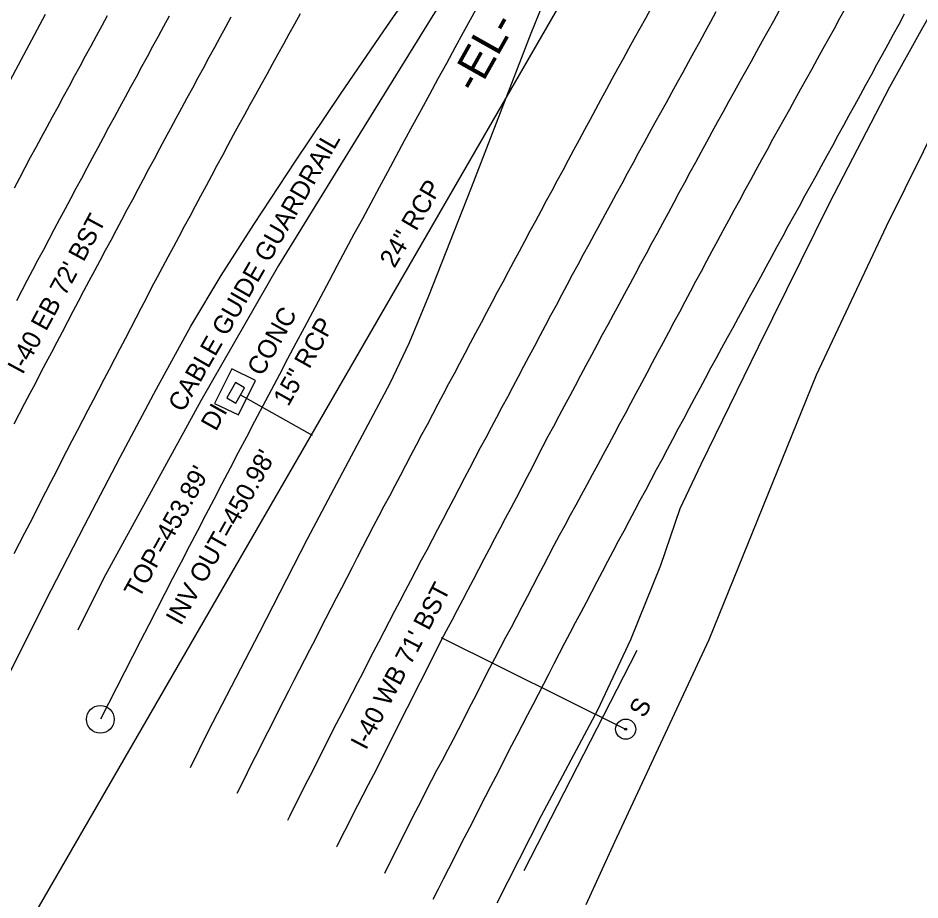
# Model space of a CAD drawing. Extents: x 2074109 to 2077820, y 741079 to 746031.
# Drawn here: x 2074752.4 to 2074948, y 741950.3 to 742141.5 of the extents above; entities that cross this region are included whole.
import ezdxf

# ---------------------------------------------------------------- set-up
doc = ezdxf.new("R2010")
doc.units = 0
for name, color, linetype in [('Exist Guardrail', 7, 'Continuous'), ('Exist Guardrail Cable Guide Rail', 7, 'Continuous'), ('Exist Guardrail Cable Guide Rail Text', 7, 'Continuous'), ('Exist Horizontal Alignment', 7, 'Continuous'), ('Exist Horizontal Alignment Direction Label', 7, 'Continuous'), ('Exist Horizontal Alignment Point', 7, 'Continuous'), ('Exist Other Culture Sign', 7, 'Continuous'), ('Exist Other Culture Sign Text', 7, 'Continuous'), ('Exist Roads EOP', 7, 'Continuous'), ('Exist Roads EOP Text', 7, 'Continuous'), ('Exist Roads EOT', 7, 'Continuous'), ('Exist Structure Minor Drop Inlet', 7, 'Continuous'), ('Exist Structure Minor Drop Inlet Text', 7, 'Continuous'), ('Exist Structure Minor Drop Inlet Top Elevation', 7, 'Continuous'), ('Exist Structure Minor Paved Ditch or Gutter', 7, 'Continuous'), ('Exist Structure Minor Paved Ditch or Gutter Text', 7, 'Continuous'), ('Exist Structure Minor Pipes RCP 15 Inch', 7, 'Continuous'), ('Exist Structure Minor Pipes RCP 15 Inch Invert', 7, 'Continuous'), ('Exist Structure Minor Pipes RCP 15 Inch Text', 7, 'Continuous'), ('Exist Structure Minor Pipes RCP 24 Inch', 7, 'Continuous'), ('Exist Structure Minor Pipes RCP 24 Inch Text', 7, 'Continuous'), ('Exist Vegetation Woods Line', 7, 'Continuous')]:
    doc.layers.add(name, color=color, linetype=linetype)

msp = doc.modelspace()

# ---------------------------------------------------------------- linework, layer by layer
at = {"layer": 'Exist Guardrail'}
msp.add_lwpolyline([(2074886.58, 742004.39), (2074862.07, 741956.61)], dxfattribs=at)
at = {"layer": 'Exist Guardrail Cable Guide Rail'}
msp.add_lwpolyline([(2074899.36, 742232.91), (2074888.78, 742216.41), (2074876.27, 742195.78), (2074859.16, 742168.78), (2074842.38, 742142.08), (2074825.57, 742114.96), (2074808.9, 742087.84), (2074792.03, 742058.51), (2074770.99, 742020.02), (2074765.4, 742008.78)], dxfattribs=at)
at = {"layer": 'Exist Horizontal Alignment'}
msp.add_arc((2079979.02, 739333.44), 5846.83, 150.58124, 152.982068, dxfattribs=at)
at = {"layer": 'Exist Horizontal Alignment Point'}
msp.add_circle((2074770.28, 741989.47), 3, dxfattribs=at)
at = {"layer": 'Exist Other Culture Sign'}
msp.add_line((2074884.22, 741987.29), (2074844.2, 742007.16), dxfattribs=at)
for radius in [2.18, 0.24]:
    msp.add_circle((2074884.17, 741987.33), radius, dxfattribs=at)
at = {"layer": 'Exist Roads EOP'}
for points in [[(2075045.28, 742485.48), (2075032.39, 742461.82), (2075017.41, 742432.2), (2075008.62, 742415.56), (2074994.4, 742390.44), (2074976.29, 742358.27), (2074960.6, 742330.46), (2074947.27, 742306.52), (2074935.38, 742284.89), (2074921.31, 742258.95), (2074908.74, 742236.47), (2074898.47, 742217.63), (2074887.04, 742193.79), (2074875.51, 742167.59), (2074863.59, 742138.18), (2074850.64, 742104.73), (2074841.42, 742081.23), (2074837.2, 742071.06), (2074833.01, 742062.28), (2074824.64, 742046.55), (2074815.15, 742028.51), (2074804.68, 742008.24), (2074793.6, 741986.73), (2074789.72, 741978.96)], [(2075094.13, 742370.13), (2075069.1, 742335.88), (2075044.09, 742299.32), (2075030.48, 742279.57), (2075015.99, 742257.41), (2075007.67, 742243.82), (2075000.77, 742231.34), (2074992.02, 742216.02), (2074980.6, 742196.16), (2074968.94, 742175.62), (2074957.17, 742154.61), (2074948.54, 742139.39), (2074941.35, 742126.55), (2074928.28, 742101.28), (2074912.89, 742070.17), (2074900.43, 742044.7), (2074895.91, 742035.09), (2074891.74, 742022.83), (2074885.19, 742006.69), (2074878.07, 741991.46), (2074865.85, 741968.56), (2074856.22, 741949.59)], [(2074750.85, 741999.99), (2074758.48, 742015.22), (2074766.83, 742031.47), (2074774.6, 742046.3), (2074782.43, 742061.13), (2074789.86, 742074.68), (2074796.45, 742085.69), (2074803.58, 742096.75), (2074812.61, 742110.46), (2074822.37, 742125.04), (2074831.71, 742138.74), (2074841.22, 742152.47)]]:
    msp.add_lwpolyline(points, dxfattribs=at)
at = {"layer": 'Exist Roads EOT'}
for points in [[(2074799.94, 741973.43), (2074801.06, 741975.66), (2074802.18, 741977.9), (2074803.29, 741980.14), (2074804.41, 741982.37), (2074805.53, 741984.61), (2074806.65, 741986.85), (2074807.78, 741989.07), (2074808.92, 741991.3), (2074810.06, 741993.52), (2074811.2, 741995.75), (2074812.33, 741997.97), (2074813.47, 742000.2), (2074814.61, 742002.42), (2074815.75, 742004.65), (2074816.89, 742006.87), (2074818.03, 742009.1), (2074819.17, 742011.33), (2074820.31, 742013.55), (2074821.46, 742015.77), (2074822.61, 742017.99), (2074823.76, 742020.21), (2074824.91, 742022.43), (2074826.06, 742024.65), (2074827.21, 742026.87), (2074828.36, 742029.09), (2074829.51, 742031.31), (2074830.67, 742033.52), (2074831.83, 742035.73), (2074833, 742037.94), (2074834.17, 742040.15), (2074835.33, 742042.36), (2074836.5, 742044.57), (2074837.67, 742046.79), (2074838.83, 742049), (2074840, 742051.21), (2074841.17, 742053.42), (2074842.33, 742055.63), (2074843.51, 742057.84), (2074844.68, 742060.05), (2074845.85, 742062.25), (2074847.02, 742064.46), (2074848.19, 742066.67), (2074849.37, 742068.88), (2074850.54, 742071.09), (2074851.71, 742073.29), (2074852.88, 742075.5), (2074854.05, 742077.71), (2074855.22, 742079.92), (2074856.4, 742082.13), (2074857.57, 742084.33), (2074858.74, 742086.54), (2074859.93, 742088.74), (2074861.11, 742090.94), (2074862.29, 742093.15), (2074863.48, 742095.35), (2074864.66, 742097.55), (2074865.84, 742099.75), (2074867.03, 742101.95), (2074868.21, 742104.15), (2074869.39, 742106.36), (2074870.58, 742108.56), (2074871.77, 742110.76), (2074872.95, 742112.96), (2074874.14, 742115.16), (2074875.32, 742117.36), (2074876.51, 742119.56), (2074877.7, 742121.76), (2074878.88, 742123.96), (2074880.07, 742126.16), (2074881.26, 742128.36), (2074882.47, 742130.55), (2074883.67, 742132.74), (2074884.88, 742134.93), (2074886.09, 742137.12), (2074887.29, 742139.3), (2074888.5, 742141.49), (2074889.71, 742143.68)], [(2074917.39, 742143.03), (2074916.18, 742140.85), (2074914.96, 742138.66), (2074913.75, 742136.47), (2074912.54, 742134.29), (2074911.33, 742132.1), (2074910.12, 742129.91), (2074908.91, 742127.73), (2074907.69, 742125.54), (2074906.48, 742123.35), (2074905.27, 742121.17), (2074904.06, 742118.98), (2074902.86, 742116.79), (2074901.66, 742114.59), (2074900.46, 742112.4), (2074899.27, 742110.2), (2074898.09, 742108), (2074896.9, 742105.8), (2074895.71, 742103.6), (2074894.53, 742101.4), (2074893.34, 742099.2), (2074892.16, 742097), (2074890.97, 742094.8), (2074889.78, 742092.6), (2074888.6, 742090.4), (2074887.41, 742088.2), (2074886.23, 742086), (2074885.04, 742083.8), (2074883.85, 742081.6), (2074882.66, 742079.4), (2074881.47, 742077.2), (2074880.28, 742075), (2074879.1, 742072.8), (2074877.92, 742070.59), (2074876.74, 742068.39), (2074875.56, 742066.18), (2074874.38, 742063.98), (2074873.2, 742061.78), (2074872.02, 742059.57), (2074870.84, 742057.37), (2074869.66, 742055.17), (2074868.48, 742052.96), (2074867.3, 742050.76), (2074866.16, 742048.54), (2074865.01, 742046.31), (2074863.86, 742044.09), (2074862.72, 742041.87), (2074861.56, 742039.66), (2074860.39, 742037.44), (2074859.23, 742035.23), (2074858.07, 742033.02), (2074856.91, 742030.8), (2074855.75, 742028.59), (2074854.59, 742026.38), (2074853.43, 742024.16), (2074852.26, 742021.95), (2074851.1, 742019.74), (2074849.94, 742017.52), (2074848.78, 742015.31), (2074847.61, 742013.1), (2074846.45, 742010.89), (2074845.28, 742008.68), (2074844.11, 742006.47), (2074842.98, 742004.23), (2074841.86, 742002), (2074840.74, 741999.77), (2074839.61, 741997.53), (2074838.49, 741995.3), (2074837.37, 741993.07), (2074836.24, 741990.84), (2074835.12, 741988.6), (2074833.99, 741986.37), (2074832.87, 741984.14), (2074831.75, 741981.9), (2074830.62, 741979.67), (2074829.47, 741977.45), (2074828.32, 741975.23), (2074827.17, 741973.01), (2074826.02, 741970.79), (2074824.9, 741968.56), (2074823.77, 741966.33), (2074822.65, 741964.1), (2074821.52, 741961.86), (2074821.48, 741961.78)], [(2074831.95, 741956.11), (2074833.07, 741958.35), (2074834.19, 741960.58), (2074835.31, 741962.82), (2074836.43, 741965.05), (2074837.55, 741967.28), (2074838.67, 741969.52), (2074839.8, 741971.75), (2074840.92, 741973.99), (2074842.08, 741976.2), (2074843.25, 741978.41), (2074844.42, 741980.62), (2074845.59, 741982.83), (2074846.76, 741985.04), (2074847.92, 741987.25), (2074849.06, 741989.48), (2074850.19, 741991.71), (2074851.32, 741993.93), (2074852.46, 741996.16), (2074853.59, 741998.39), (2074854.72, 742000.62), (2074855.88, 742002.83), (2074857.05, 742005.05), (2074858.21, 742007.26), (2074859.38, 742009.47), (2074860.54, 742011.68), (2074861.71, 742013.89), (2074862.86, 742016.11), (2074864.02, 742018.32), (2074865.18, 742020.54), (2074866.33, 742022.76), (2074867.49, 742024.97), (2074868.65, 742027.19), (2074869.85, 742029.38), (2074871.04, 742031.58), (2074872.23, 742033.78), (2074873.42, 742035.98), (2074874.62, 742038.17), (2074875.81, 742040.37), (2074877, 742042.57), (2074878.19, 742044.76), (2074879.38, 742046.97), (2074880.55, 742049.17), (2074881.73, 742051.38), (2074882.91, 742053.58), (2074884.09, 742055.78), (2074885.27, 742057.99), (2074886.45, 742060.19), (2074887.63, 742062.4), (2074888.81, 742064.6), (2074889.99, 742066.81), (2074891.16, 742069.01), (2074892.34, 742071.22), (2074893.52, 742073.42), (2074894.69, 742075.63), (2074895.87, 742077.83), (2074897.05, 742080.04), (2074898.22, 742082.25), (2074899.4, 742084.45), (2074900.57, 742086.66), (2074901.75, 742088.86), (2074902.93, 742091.07), (2074904.12, 742093.27), (2074905.31, 742095.46), (2074906.51, 742097.66), (2074907.7, 742099.85), (2074908.9, 742102.05), (2074910.09, 742104.25), (2074911.29, 742106.44), (2074912.48, 742108.64), (2074913.68, 742110.83), (2074914.87, 742113.03), (2074916.09, 742115.22), (2074917.3, 742117.4), (2074918.51, 742119.59), (2074919.72, 742121.78), (2074920.93, 742123.96), (2074922.14, 742126.15), (2074923.35, 742128.34), (2074924.56, 742130.53), (2074925.77, 742132.71), (2074926.98, 742134.9), (2074928.19, 742137.09), (2074929.41, 742139.27), (2074930.62, 742141.46), (2074931.83, 742143.64)], [(2074758.35, 742142.29), (2074749.53, 742125.74)], [(2074813.59, 742142.41), (2074812.38, 742140.22), (2074811.17, 742138.03), (2074809.96, 742135.85), (2074808.76, 742133.66), (2074807.55, 742131.47), (2074806.34, 742129.28), (2074805.13, 742127.09), (2074803.93, 742124.9), (2074802.72, 742122.71), (2074801.51, 742120.52), (2074800.3, 742118.33), (2074799.1, 742116.15), (2074797.92, 742113.94), (2074796.74, 742111.74), (2074795.56, 742109.53), (2074794.38, 742107.33), (2074793.19, 742105.13), (2074792.01, 742102.92), (2074790.83, 742100.72), (2074789.65, 742098.52), (2074788.47, 742096.31), (2074787.29, 742094.11), (2074786.11, 742091.91), (2074784.93, 742089.7), (2074783.75, 742087.5), (2074782.57, 742085.3), (2074781.4, 742083.08), (2074780.25, 742080.87), (2074779.1, 742078.65), (2074777.95, 742076.43), (2074776.79, 742074.21), (2074775.64, 742071.99), (2074774.49, 742069.78), (2074773.33, 742067.56), (2074772.18, 742065.34), (2074771.03, 742063.12), (2074769.87, 742060.9), (2074768.72, 742058.69), (2074767.57, 742056.47), (2074766.41, 742054.25), (2074765.26, 742052.03), (2074764.11, 742049.81), (2074762.96, 742047.6), (2074761.81, 742045.37), (2074760.67, 742043.15), (2074759.54, 742040.92), (2074758.4, 742038.7), (2074757.26, 742036.47), (2074756.12, 742034.25), (2074754.98, 742032.02), (2074753.84, 742029.8), (2074752.7, 742027.57), (2074751.56, 742025.35)], [(2074751.62, 742053.56), (2074752.78, 742055.77), (2074753.94, 742057.99), (2074755.1, 742060.2), (2074756.26, 742062.42), (2074757.41, 742064.63), (2074758.57, 742066.85), (2074759.73, 742069.06), (2074760.89, 742071.28), (2074762.05, 742073.5), (2074763.2, 742075.71), (2074764.36, 742077.93), (2074765.53, 742080.14), (2074766.7, 742082.34), (2074767.88, 742084.55), (2074769.06, 742086.75), (2074770.23, 742088.96), (2074771.41, 742091.17), (2074772.59, 742093.37), (2074773.76, 742095.58), (2074774.94, 742097.78), (2074776.12, 742099.99), (2074777.29, 742102.19), (2074778.47, 742104.4), (2074779.65, 742106.6), (2074780.82, 742108.81), (2074781.99, 742111.02), (2074783.16, 742113.23), (2074784.34, 742115.43), (2074785.53, 742117.63), (2074786.73, 742119.83), (2074787.92, 742122.02), (2074789.12, 742124.22), (2074790.31, 742126.41), (2074791.5, 742128.61), (2074792.7, 742130.81), (2074793.89, 742133), (2074795.09, 742135.2), (2074796.28, 742137.39), (2074797.48, 742139.59), (2074798.67, 742141.79)], [(2074751.64, 742104.7), (2074752.82, 742106.9), (2074753.99, 742109.11), (2074755.17, 742111.32), (2074756.35, 742113.52), (2074757.54, 742115.72), (2074758.73, 742117.91), (2074759.93, 742120.11), (2074761.12, 742122.3), (2074762.32, 742124.5), (2074763.52, 742126.69), (2074764.71, 742128.89), (2074765.9, 742131.09), (2074767.09, 742133.29), (2074768.28, 742135.49), (2074769.47, 742137.68), (2074770.66, 742139.88), (2074771.84, 742142.08)], [(2074785.18, 742141.92), (2074783.99, 742139.72), (2074782.8, 742137.52), (2074781.61, 742135.33), (2074780.42, 742133.13), (2074779.22, 742130.93), (2074778.03, 742128.73), (2074776.84, 742126.54), (2074775.65, 742124.34), (2074774.46, 742122.14), (2074773.27, 742119.94), (2074772.08, 742117.75), (2074770.89, 742115.55), (2074769.7, 742113.35), (2074768.51, 742111.15), (2074767.34, 742108.94), (2074766.16, 742106.74), (2074764.99, 742104.53), (2074763.81, 742102.32), (2074762.64, 742100.12), (2074761.46, 742097.91), (2074760.28, 742095.71), (2074759.11, 742093.5), (2074757.93, 742091.29), (2074756.76, 742089.09), (2074755.58, 742086.88), (2074754.41, 742084.67), (2074753.26, 742082.45), (2074752.12, 742080.23)], [(2074903.73, 742142.87), (2074902.53, 742140.68), (2074901.33, 742138.48), (2074900.13, 742136.29), (2074898.93, 742134.1), (2074897.73, 742131.9), (2074896.53, 742129.71), (2074895.33, 742127.52), (2074894.13, 742125.33), (2074892.91, 742123.14), (2074891.69, 742120.96), (2074890.48, 742118.77), (2074889.28, 742116.58), (2074888.09, 742114.38), (2074886.89, 742112.19), (2074885.7, 742109.99), (2074884.51, 742107.79), (2074883.31, 742105.6), (2074882.12, 742103.4), (2074880.93, 742101.21), (2074879.73, 742099.01), (2074878.54, 742096.81), (2074877.35, 742094.62), (2074876.15, 742092.42), (2074874.96, 742090.22), (2074873.78, 742088.02), (2074872.59, 742085.82), (2074871.41, 742083.62), (2074870.23, 742081.41), (2074869.06, 742079.2), (2074867.89, 742077), (2074866.72, 742074.79), (2074865.54, 742072.58), (2074864.37, 742070.37), (2074863.2, 742068.16), (2074862.03, 742065.95), (2074860.86, 742063.75), (2074859.69, 742061.54), (2074858.51, 742059.33), (2074857.34, 742057.12), (2074856.17, 742054.91), (2074854.99, 742052.71), (2074853.82, 742050.5), (2074852.64, 742048.3), (2074851.48, 742046.08), (2074850.31, 742043.87), (2074849.15, 742041.66), (2074847.99, 742039.44), (2074846.83, 742037.23), (2074845.67, 742035.02), (2074844.5, 742032.8), (2074843.34, 742030.59), (2074842.18, 742028.38), (2074841.02, 742026.16), (2074839.86, 742023.95), (2074838.69, 742021.74), (2074837.53, 742019.52), (2074836.37, 742017.31), (2074835.21, 742015.1), (2074834.05, 742012.88), (2074832.9, 742010.66), (2074831.75, 742008.44), (2074830.6, 742006.22), (2074829.45, 742004), (2074828.3, 742001.78), (2074827.15, 741999.56), (2074826.01, 741997.34), (2074824.86, 741995.12), (2074823.71, 741992.9), (2074822.56, 741990.68), (2074821.41, 741988.46), (2074820.26, 741986.24), (2074819.14, 741984.01), (2074818.01, 741981.78), (2074816.89, 741979.54), (2074815.76, 741977.31), (2074814.64, 741975.08), (2074813.51, 741972.85), (2074812.39, 741970.61), (2074811.27, 741968.38), (2074810.84, 741967.53)], [(2074842.42, 741950.45), (2074843.55, 741952.68), (2074844.68, 741954.91), (2074845.82, 741957.13), (2074846.96, 741959.36), (2074848.1, 741961.58), (2074849.24, 741963.81), (2074850.37, 741966.03), (2074851.51, 741968.26), (2074852.65, 741970.48), (2074853.79, 741972.71), (2074854.93, 741974.94), (2074856.07, 741977.16), (2074857.21, 741979.39), (2074858.35, 741981.61), (2074859.5, 741983.83), (2074860.65, 741986.05), (2074861.8, 741988.27), (2074862.95, 741990.49), (2074864.1, 741992.71), (2074865.25, 741994.93), (2074866.4, 741997.15), (2074867.54, 741999.37), (2074868.69, 742001.59), (2074869.84, 742003.81), (2074870.99, 742006.03), (2074872.15, 742008.25), (2074873.31, 742010.46), (2074874.48, 742012.67), (2074875.64, 742014.88), (2074876.8, 742017.09), (2074877.97, 742019.31), (2074879.13, 742021.52), (2074880.3, 742023.73), (2074881.46, 742025.94), (2074882.63, 742028.16), (2074883.8, 742030.36), (2074884.97, 742032.57), (2074886.15, 742034.77), (2074887.33, 742036.98), (2074888.51, 742039.18), (2074889.69, 742041.39), (2074890.86, 742043.6), (2074892.04, 742045.8), (2074893.22, 742048.01), (2074894.4, 742050.21), (2074895.57, 742052.42), (2074896.75, 742054.62), (2074897.93, 742056.83), (2074899.11, 742059.03), (2074900.29, 742061.24), (2074901.46, 742063.44), (2074902.64, 742065.65), (2074903.84, 742067.84), (2074905.03, 742070.04), (2074906.23, 742072.23), (2074907.43, 742074.42), (2074908.63, 742076.62), (2074909.83, 742078.81), (2074911.03, 742081), (2074912.23, 742083.2), (2074913.43, 742085.39), (2074914.63, 742087.58), (2074915.82, 742089.78), (2074917.02, 742091.97), (2074918.22, 742094.17), (2074919.42, 742096.36), (2074920.62, 742098.55), (2074921.82, 742100.74), (2074923.03, 742102.94), (2074924.23, 742105.13), (2074925.43, 742107.32), (2074926.63, 742109.51), (2074927.83, 742111.7), (2074929.04, 742113.9), (2074930.24, 742116.09), (2074931.44, 742118.28), (2074932.64, 742120.47), (2074933.84, 742122.66), (2074935.05, 742124.86), (2074936.24, 742127.05), (2074937.44, 742129.24), (2074938.64, 742131.44), (2074939.84, 742133.63), (2074941.04, 742135.82), (2074942.24, 742138.02), (2074943.44, 742140.21), (2074944.64, 742142.4)]]:
    msp.add_lwpolyline(points, dxfattribs=at)
at = {"layer": 'Exist Structure Minor Drop Inlet'}
msp.add_lwpolyline([(2074799.62, 742058.04), (2074801.52, 742061.37), (2074799.58, 742062.48), (2074797.67, 742059.14)], close=True, dxfattribs=at)
at = {"layer": 'Exist Structure Minor Paved Ditch or Gutter'}
msp.add_lwpolyline([(2074800.2, 742055.46), (2074803.93, 742062.92), (2074798.79, 742065.48), (2074795.04, 742057.93), (2074800.2, 742055.46)], dxfattribs=at)
at = {"layer": 'Exist Structure Minor Pipes RCP 15 Inch'}
msp.add_line((2074800.49, 742059.87), (2074816.22, 742051.09), dxfattribs=at)
at = {"layer": 'Exist Structure Minor Pipes RCP 24 Inch'}
msp.add_line((2074709.57, 741866.73), (2074933.64, 742254.78), dxfattribs=at)
at = {"layer": 'Exist Vegetation Woods Line'}
msp.add_lwpolyline([(2074875.58, 741949.31), (2074881.78, 741962.92), (2074902.24, 742006.78), (2074925.54, 742064.16), (2074940.68, 742096.37), (2074960.82, 742136.95), (2074983.57, 742182.77), (2074996.02, 742207.83), (2075008.83, 742226.84), (2075023.38, 742228.2), (2075034.28, 742231.24), (2075042.51, 742239.25), (2075051.73, 742246.9), (2075071.81, 742241.83), (2075093.56, 742234.23), (2075099.27, 742231.29), (2075098.5, 742221.92), (2075090.59, 742198.49), (2075086.7, 742178.53), (2075085.38, 742160.72)], dxfattribs=at)

# ---------------------------------------------------------------- texts
at = {"layer": 'Exist Guardrail Cable Guide Rail Text'}
msp.add_text('CABLE GUIDE GUARDRAIL', height=4, rotation=60.0874, dxfattribs=at).set_placement((2074788.18, 742055.83))
at = {"layer": 'Exist Horizontal Alignment Direction Label'}
msp.add_text('-EL-', height=7, rotation=60.6268, dxfattribs=at).set_placement((2074851.83, 742124.91))
at = {"layer": 'Exist Other Culture Sign Text'}
msp.add_text('S', height=4, rotation=60.742, dxfattribs=at).set_placement((2074888.17, 741989.57))
at = {"layer": 'Exist Roads EOP Text'}
for s, rotation, p in [("I-40 EB 72' BST", 61.6166, (2074753.43, 742064.04)), ("I-40 WB 71' BST", 62.2639, (2074827.85, 741982.61))]:
    msp.add_text(s, height=4, rotation=rotation, dxfattribs=at).set_placement(p)
at = {"layer": 'Exist Structure Minor Drop Inlet Text'}
msp.add_text('DI', height=4, rotation=60.7411, dxfattribs=at).set_placement((2074795.34, 742051.75))
at = {"layer": 'Exist Structure Minor Drop Inlet Top Elevation'}
msp.add_text("TOP=453.89'", height=4, rotation=60.742, dxfattribs=at).set_placement((2074778.68, 742015.46))
at = {"layer": 'Exist Structure Minor Paved Ditch or Gutter Text'}
msp.add_text('CONC', height=4, rotation=60.742, dxfattribs=at).set_placement((2074805.34, 742063.65))
at = {"layer": 'Exist Structure Minor Pipes RCP 15 Inch Invert'}
msp.add_text("INV OUT=450.98'", height=4, rotation=60.742, dxfattribs=at).set_placement((2074787.73, 742009.61))
at = {"layer": 'Exist Structure Minor Pipes RCP 15 Inch Text'}
msp.add_text('15" RCP', height=4, rotation=60.742, dxfattribs=at).set_placement((2074811.02, 742057.11))
at = {"layer": 'Exist Structure Minor Pipes RCP 24 Inch Text'}
msp.add_text('24" RCP', height=4, rotation=59.6812, dxfattribs=at).set_placement((2074834.03, 742087.1))

doc.saveas('drawing.dxf')
